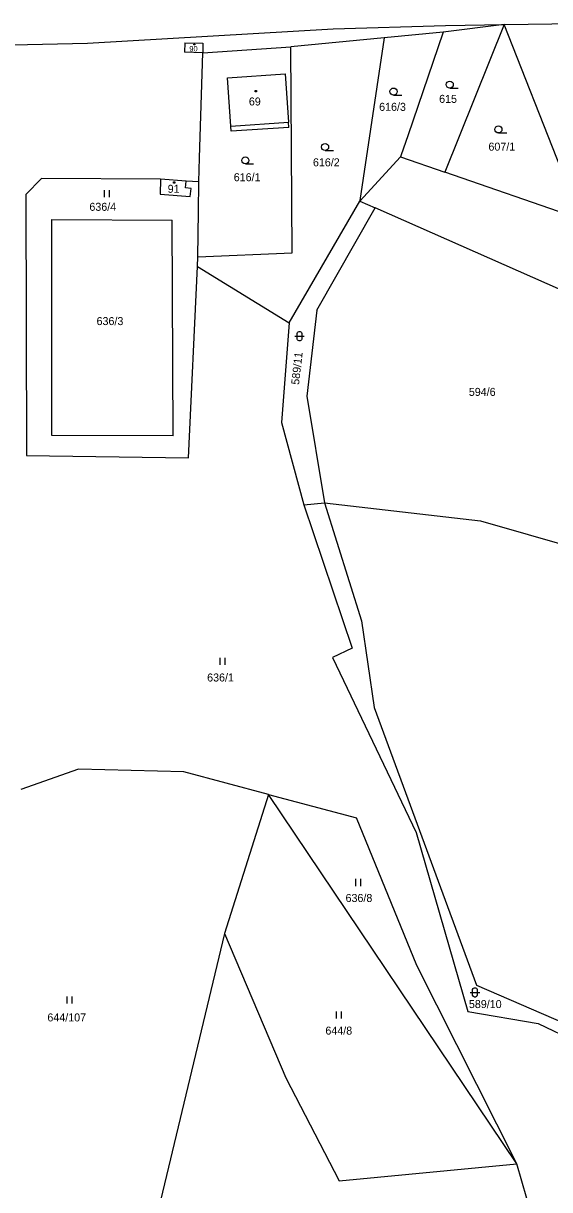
# Model space of a CAD drawing. Extents: x -791032 to -787751, y -1106872 to -1104403.
# Drawn here: x -789189 to -789077.2, y -1105471.5 to -1105223.7 of the extents above; entities that cross this region are included whole.
import ezdxf

# ---------------------------------------------------------------- set-up
doc = ezdxf.new("R2010")
doc.units = 0
for name, color, linetype in [('Vrstva 1', 7, 'Continuous'), ('Vrstva 14', 7, 'Continuous'), ('Vrstva 15', 7, 'Continuous'), ('Vrstva 2', 7, 'Continuous'), ('Vrstva 23', 7, 'Continuous'), ('Vrstva 25', 7, 'Continuous')]:
    doc.layers.add(name, color=color, linetype=linetype)

msp = doc.modelspace()

# ---------------------------------------------------------------- linework, layer by layer
at = {"layer": 'Vrstva 1'}
for p, q in [((-789175.36, -1105227.85), (-789123.13, -1105224.85)), ((-789123.13, -1105224.85), (-789099.3, -1105224.13)), ((-789086.8, -1105223.93), (-789099.82, -1105225.53)), ((-789086.8, -1105223.93), (-789099.4, -1105255.27)), ((-789099.3, -1105224.13), (-789086.8, -1105223.93)), ((-789086.8, -1105223.93), (-789070.73, -1105223.67)), ((-789074.73, -1105254.68), (-789086.8, -1105223.93)), ((-789112.32, -1105226.74), (-789132.19, -1105228.66)), ((-789099.82, -1105225.53), (-789112.32, -1105226.74)), ((-789222.94, -1105228.96), (-789175.36, -1105227.85)), ((-789154.67, -1105227.81), (-789154.72, -1105229.83)), ((-789150.88, -1105229.93), (-789154.72, -1105229.83)), ((-789154.67, -1105227.81), (-789150.83, -1105227.91)), ((-789151.6, -1105252.26), (-789150.88, -1105229.93)), ((-789150.83, -1105227.91), (-789150.88, -1105229.93)), ((-789150.88, -1105229.93), (-789132.19, -1105228.66)), ((-789131.85, -1105272.41), (-789132.19, -1105228.66)), ((-789145.61, -1105235.23), (-789133.34, -1105234.41)), ((-789133.34, -1105234.41), (-789132.65, -1105244.68)), ((-789144.92, -1105245.5), (-789145.61, -1105235.23)), ((-789132.58, -1105245.78), (-789132.65, -1105244.68)), ((-789144.85, -1105246.6), (-789144.92, -1105245.5)), ((-789132.58, -1105245.78), (-789144.85, -1105246.6)), ((-789151.68, -1105257.38), (-789151.6, -1105252.26)), ((-789117.51, -1105261.43), (-789108.83, -1105252)), ((-789108.83, -1105252), (-789099.4, -1105255.27)), ((-789185.12, -1105256.66), (-789188.46, -1105260.01)), ((-789159.84, -1105256.77), (-789185.12, -1105256.66)), ((-789159.84, -1105256.77), (-789159.93, -1105259.94)), ((-789154.39, -1105257.18), (-789159.84, -1105256.77)), ((-789154.56, -1105258.63), (-789154.39, -1105257.18)), ((-789151.68, -1105257.38), (-789154.39, -1105257.18)), ((-789151.77, -1105263.71), (-789151.68, -1105257.38)), ((-789066.71, -1105266.61), (-789099.4, -1105255.27)), ((-789153.37, -1105258.77), (-789154.56, -1105258.63)), ((-789153.57, -1105260.44), (-789153.37, -1105258.77)), ((-789188.46, -1105260.01), (-789188.36, -1105315.51)), ((-789159.93, -1105259.94), (-789153.57, -1105260.44)), ((-789132.5, -1105287.3), (-789117.51, -1105261.43)), ((-789117.51, -1105261.43), (-789114.21, -1105262.89)), ((-789151.93, -1105273.29), (-789151.77, -1105263.71)), ((-789126.65, -1105284.61), (-789114.21, -1105262.89)), ((-789039.51, -1105295.94), (-789114.21, -1105262.89)), ((-789182.95, -1105265.32), (-789157.35, -1105265.46)), ((-789182.93, -1105311.21), (-789182.95, -1105265.32)), ((-789157.14, -1105311.29), (-789157.35, -1105265.46)), ((-789151.96, -1105275.33), (-789151.93, -1105273.29)), ((-789151.93, -1105273.29), (-789131.85, -1105272.41)), ((-789153.87, -1105315.99), (-789151.96, -1105275.33)), ((-789151.96, -1105275.33), (-789132.5, -1105287.3)), ((-789126.65, -1105284.61), (-789128.73, -1105302.91)), ((-789132.5, -1105287.3), (-789134.12, -1105308.5)), ((-789128.73, -1105302.91), (-789124.99, -1105325.56)), ((-789134.12, -1105308.5), (-789129.4, -1105325.94)), ((-789157.14, -1105311.29), (-789182.93, -1105311.21)), ((-789188.36, -1105315.51), (-789153.87, -1105315.99)), ((-789129.4, -1105325.94), (-789124.99, -1105325.56)), ((-789129.4, -1105325.94), (-789119.16, -1105356.45)), ((-789124.99, -1105325.56), (-789091.87, -1105329.34)), ((-789124.99, -1105325.56), (-789117.12, -1105350.58)), ((-789091.87, -1105329.34), (-789059.86, -1105338.55)), ((-789117.12, -1105350.58), (-789114.45, -1105369.04)), ((-789119.16, -1105356.45), (-789123.27, -1105358.39)), ((-789123.27, -1105358.39), (-789105.5, -1105395.61)), ((-789114.45, -1105369.04), (-789092.69, -1105427.98)), ((-789177.3, -1105382.12), (-789189.55, -1105386.43)), ((-789154.92, -1105382.66), (-789177.3, -1105382.12)), ((-789136.87, -1105387.48), (-789154.92, -1105382.66)), ((-789136.87, -1105387.48), (-789146.23, -1105417.04)), ((-789084.1, -1105466), (-789136.87, -1105387.48)), ((-789136.87, -1105387.48), (-789118.23, -1105392.46)), ((-789105.37, -1105423.82), (-789118.23, -1105392.46)), ((-789105.5, -1105395.61), (-789094.58, -1105433.62)), ((-789146.23, -1105417.04), (-789163.41, -1105488.56)), ((-789146.23, -1105417.04), (-789133.21, -1105447.71)), ((-789084.1, -1105466), (-789105.37, -1105423.82)), ((-789092.69, -1105427.98), (-789063.07, -1105440.87)), ((-789094.58, -1105433.62), (-789079.58, -1105436.15)), ((-789079.58, -1105436.15), (-789064.43, -1105443.48)), ((-789133.21, -1105447.71), (-789121.86, -1105469.6)), ((-789121.86, -1105469.6), (-789084.1, -1105466)), ((-789068.11, -1105521.62), (-789084.1, -1105466))]:
    msp.add_line(p, q, dxfattribs=at)
for points in [[(-789112.32, -1105226.74), (-789116.78, -1105256.56), (-789117.49, -1105261.29), (-789117.51, -1105261.43)], [(-789099.82, -1105225.53), (-789107.32, -1105247.55), (-789108.7, -1105251.61), (-789108.83, -1105252)]]:
    msp.add_lwpolyline(points, dxfattribs=at)
at = {"layer": 'Vrstva 2'}
msp.add_line((-789144.92, -1105245.5), (-789132.65, -1105244.68), dxfattribs=at)
at = {"layer": 'Vrstva 23'}
for p, q in [((-789098.38, -1105237.44), (-789096.63, -1105237.44)), ((-789110.34, -1105238.91), (-789108.59, -1105238.91)), ((-789088.04, -1105246.97), (-789086.29, -1105246.97)), ((-789124.87, -1105250.69), (-789123.12, -1105250.69)), ((-789141.82, -1105253.54), (-789140.07, -1105253.54)), ((-789171.74, -1105260.59), (-789171.74, -1105259.09)), ((-789170.74, -1105259.09), (-789170.74, -1105260.59)), ((-789130.81, -1105289.54), (-789130.71, -1105289.34)), ((-789130.81, -1105290.74), (-789130.81, -1105289.54)), ((-789130.71, -1105289.34), (-789130.61, -1105289.24)), ((-789130.61, -1105289.24), (-789130.41, -1105289.14)), ((-789130.41, -1105289.14), (-789130.21, -1105289.14)), ((-789130.21, -1105289.14), (-789130.01, -1105289.24)), ((-789130.01, -1105289.24), (-789129.91, -1105289.34)), ((-789129.91, -1105289.34), (-789129.81, -1105289.54)), ((-789129.81, -1105289.54), (-789129.81, -1105290.74)), ((-789131.31, -1105290.14), (-789129.31, -1105290.14)), ((-789130.71, -1105290.94), (-789130.81, -1105290.74)), ((-789130.61, -1105291.04), (-789130.71, -1105290.94)), ((-789130.41, -1105291.14), (-789130.61, -1105291.04)), ((-789130.21, -1105291.14), (-789130.41, -1105291.14)), ((-789130.01, -1105291.04), (-789130.21, -1105291.14)), ((-789129.91, -1105290.94), (-789130.01, -1105291.04)), ((-789129.81, -1105290.74), (-789129.91, -1105290.94)), ((-789147.18, -1105359.99), (-789147.18, -1105358.49)), ((-789146.18, -1105358.49), (-789146.18, -1105359.99)), ((-789118.37, -1105406.96), (-789118.37, -1105405.46)), ((-789117.37, -1105405.46), (-789117.37, -1105406.96)), ((-789179.69, -1105431.91), (-789179.69, -1105430.41)), ((-789178.69, -1105430.41), (-789178.69, -1105431.91)), ((-789094.03, -1105429.55), (-789092.03, -1105429.55)), ((-789093.53, -1105428.95), (-789093.43, -1105428.75)), ((-789093.53, -1105430.15), (-789093.53, -1105428.95)), ((-789093.43, -1105430.35), (-789093.53, -1105430.15)), ((-789093.43, -1105428.75), (-789093.33, -1105428.65)), ((-789093.33, -1105430.45), (-789093.43, -1105430.35)), ((-789093.33, -1105428.65), (-789093.13, -1105428.55)), ((-789093.13, -1105430.55), (-789093.33, -1105430.45)), ((-789093.13, -1105428.55), (-789092.93, -1105428.55)), ((-789092.93, -1105430.55), (-789093.13, -1105430.55)), ((-789092.93, -1105428.55), (-789092.73, -1105428.65)), ((-789092.73, -1105430.45), (-789092.93, -1105430.55)), ((-789092.73, -1105428.65), (-789092.63, -1105428.75)), ((-789092.63, -1105430.35), (-789092.73, -1105430.45)), ((-789092.63, -1105428.75), (-789092.53, -1105428.95)), ((-789092.53, -1105430.15), (-789092.63, -1105430.35)), ((-789092.53, -1105428.95), (-789092.53, -1105430.15)), ((-789122.45, -1105435.1), (-789122.45, -1105433.6)), ((-789121.45, -1105433.6), (-789121.45, -1105435.1))]:
    msp.add_line(p, q, dxfattribs=at)
for centre in [(-789110.34, -1105238.16), (-789098.38, -1105236.69), (-789088.04, -1105246.22), (-789124.87, -1105249.94), (-789141.82, -1105252.79)]:
    msp.add_circle(centre, 0.75, dxfattribs=at)
at = {"layer": 'Vrstva 25'}
for p, q in [((-789152.767, -1105228.063), (-789152.566, -1105228.063)), ((-789152.767, -1105228.264), (-789152.767, -1105228.063)), ((-789152.566, -1105228.264), (-789152.767, -1105228.264)), ((-789152.566, -1105228.063), (-789152.566, -1105228.264)), ((-789139.75, -1105237.92), (-789139.45, -1105237.92)), ((-789139.75, -1105238.22), (-789139.75, -1105237.92)), ((-789139.45, -1105238.22), (-789139.75, -1105238.22)), ((-789139.45, -1105237.92), (-789139.45, -1105238.22)), ((-789157.09, -1105257.34), (-789156.79, -1105257.34)), ((-789157.09, -1105257.64), (-789157.09, -1105257.34)), ((-789156.79, -1105257.34), (-789156.79, -1105257.64)), ((-789156.79, -1105257.64), (-789157.09, -1105257.64))]:
    msp.add_line(p, q, dxfattribs=at)

# ---------------------------------------------------------------- texts
at = {"layer": 'Vrstva 14'}
for s, p in [('615', (-789100.646, -1105240.57)), ('616/3', (-789113.393, -1105242.26)), ('607/1', (-789090.169, -1105250.72)), ('616/2', (-789127.463, -1105254.05)), ('616/1', (-789144.296, -1105257.22)), ('636/4', (-789174.966, -1105263.5)), ('636/3', (-789173.44, -1105287.78)), ('594/6', (-789094.332, -1105302.82)), ('636/1', (-789149.943, -1105363.5)), ('636/8', (-789120.53, -1105410.34)), ('589/10', (-789094.318, -1105432.88)), ('644/107', (-789183.89, -1105435.72)), ('644/8', (-789124.811, -1105438.52))]:
    msp.add_text(s, height=1.7, dxfattribs=at).set_placement(p)
msp.add_text('589/11', height=1.7, rotation=83.59758, dxfattribs=at).set_placement((-789130.412, -1105300.519))
at = {"layer": 'Vrstva 15'}
for s, height, p in [('90', 1.14, (-789153.723, -1105229.64)), ('69', 1.7, (-789141.077, -1105241.12)), ('91', 1.7, (-789158.33, -1105259.67))]:
    msp.add_text(s, height=height, dxfattribs=at).set_placement(p)

doc.saveas('drawing.dxf')
